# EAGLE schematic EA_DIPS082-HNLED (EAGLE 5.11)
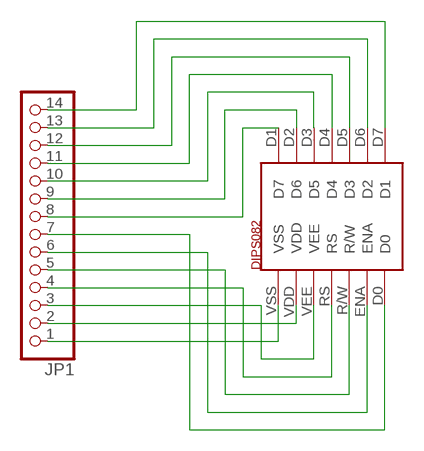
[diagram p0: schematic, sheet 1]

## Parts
JP1  PINHD-1X14  [1X14]
U$1  DIPS082  [DIPS082]

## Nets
N$1: JP1.1 U$1.VSS
N$2: JP1.2 U$1.VDD
N$3: JP1.3 U$1.VEE
N$4: JP1.4 U$1.RS
N$5: JP1.5 U$1.R/W
N$6: JP1.6 U$1.ENA
N$7: JP1.7 U$1.D0
N$8: JP1.8 U$1.D1(D7)
N$9: JP1.9 U$1.D2(D6)
N$10: JP1.10 U$1.D3(D5)
N$11: JP1.11 U$1.D4
N$12: JP1.12 U$1.D5(D3)
N$13: JP1.13 U$1.D6(D2)
N$14: JP1.14 U$1.D7(D1)

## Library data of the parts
JP1 = pinhead:PINHD-1X14: PIN HEADER
U$1 = dips082:DIPS082: Electronic Assembly 8x2 LCD displays w/w.o. backlit http://www.electronic-assembly.de/ Data sheet: http://www.electronic-assembly.de/deu/pdf/doma/dips082.pdf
